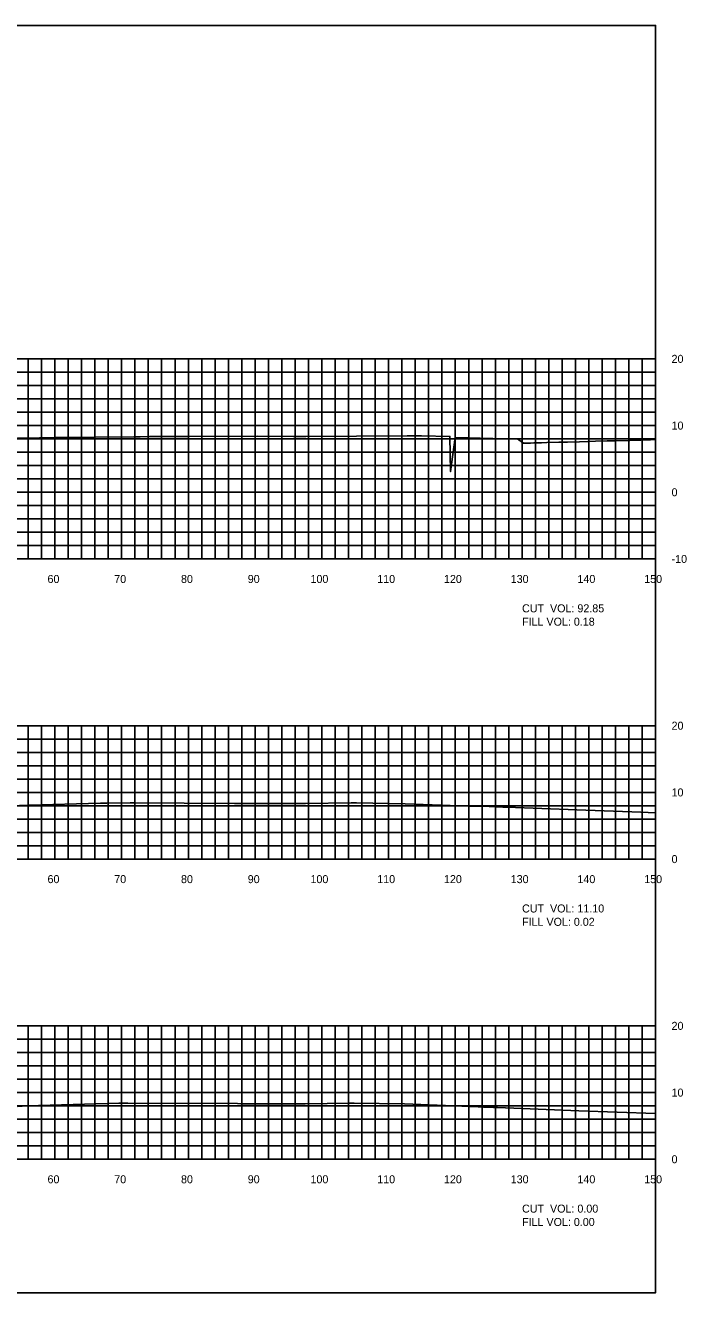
# Model space of a CAD drawing. Extents: x 1800876 to 1802446, y 250079 to 250269.
# Drawn here: x 1802346.6 to 1802445.7, y 250079.4 to 250269.4 of the extents above; entities that cross this region are included whole.
import ezdxf

# ---------------------------------------------------------------- set-up
doc = ezdxf.new("R2010")
doc.units = 0
for name, color, linetype in [('10', 7, 'Continuous'), ('31', 7, 'Continuous'), ('60', 7, 'Continuous'), ('ANNO-TXT', 7, 'Continuous'), ('Level 62', 7, 'Continuous'), ('M-ROADS', 7, 'Continuous')]:
    doc.layers.add(name, color=color, linetype=linetype)

msp = doc.modelspace()

# ---------------------------------------------------------------- linework, layer by layer
msp.add_lwpolyline([(1802141, 250079.43), (1802441, 250079.43), (1802441, 250269.43), (1802141, 250269.43)], close=True)
at = {"layer": '60'}
for p, q in [((1802441, 250189.43), (1802441, 250219.43)), ((1802441.06, 250219.43), (1802441, 250219.43)), ((1802441.06, 250209.43), (1802441, 250209.43)), ((1802441.06, 250199.43), (1802441, 250199.43)), ((1802141, 250189.43), (1802441, 250189.43)), ((1802351, 250189.37), (1802351, 250189.43)), ((1802361, 250189.37), (1802361, 250189.43)), ((1802371, 250189.37), (1802371, 250189.43)), ((1802381, 250189.37), (1802381, 250189.43)), ((1802391, 250189.37), (1802391, 250189.43)), ((1802401, 250189.37), (1802401, 250189.43)), ((1802411, 250189.37), (1802411, 250189.43)), ((1802421, 250189.37), (1802421, 250189.43)), ((1802431, 250189.37), (1802431, 250189.43)), ((1802441, 250189.37), (1802441, 250189.43)), ((1802441.06, 250189.43), (1802441, 250189.43)), ((1802441, 250144.43), (1802441, 250164.43)), ((1802441.06, 250164.43), (1802441, 250164.43)), ((1802441.06, 250154.43), (1802441, 250154.43)), ((1802141, 250144.43), (1802441, 250144.43)), ((1802351, 250144.37), (1802351, 250144.43)), ((1802361, 250144.37), (1802361, 250144.43)), ((1802371, 250144.37), (1802371, 250144.43)), ((1802381, 250144.37), (1802381, 250144.43)), ((1802391, 250144.37), (1802391, 250144.43)), ((1802401, 250144.37), (1802401, 250144.43)), ((1802411, 250144.37), (1802411, 250144.43)), ((1802421, 250144.37), (1802421, 250144.43)), ((1802431, 250144.37), (1802431, 250144.43)), ((1802441, 250144.37), (1802441, 250144.43)), ((1802441.06, 250144.43), (1802441, 250144.43)), ((1802441, 250099.43), (1802441, 250119.43)), ((1802441.06, 250119.43), (1802441, 250119.43)), ((1802441.06, 250109.43), (1802441, 250109.43)), ((1802141, 250099.43), (1802441, 250099.43)), ((1802351, 250099.37), (1802351, 250099.43)), ((1802361, 250099.37), (1802361, 250099.43)), ((1802371, 250099.37), (1802371, 250099.43)), ((1802381, 250099.37), (1802381, 250099.43)), ((1802391, 250099.37), (1802391, 250099.43)), ((1802401, 250099.37), (1802401, 250099.43)), ((1802411, 250099.37), (1802411, 250099.43)), ((1802421, 250099.37), (1802421, 250099.43)), ((1802431, 250099.37), (1802431, 250099.43)), ((1802441, 250099.37), (1802441, 250099.43)), ((1802441.06, 250099.43), (1802441, 250099.43))]:
    msp.add_line(p, q, dxfattribs=at)
at = {"layer": 'Level 62'}
for p, q in [((1802141, 250219.43), (1802441, 250219.43)), ((1802347, 250189.43), (1802347, 250219.43)), ((1802349, 250189.43), (1802349, 250219.43)), ((1802351, 250189.43), (1802351, 250219.43)), ((1802353, 250189.43), (1802353, 250219.43)), ((1802355, 250189.43), (1802355, 250219.43)), ((1802357, 250189.43), (1802357, 250219.43)), ((1802359, 250189.43), (1802359, 250219.43)), ((1802361, 250189.43), (1802361, 250219.43)), ((1802363, 250189.43), (1802363, 250219.43)), ((1802365, 250189.43), (1802365, 250219.43)), ((1802367, 250189.43), (1802367, 250219.43)), ((1802369, 250189.43), (1802369, 250219.43)), ((1802371, 250189.43), (1802371, 250219.43)), ((1802373, 250189.43), (1802373, 250219.43)), ((1802375, 250189.43), (1802375, 250219.43)), ((1802377, 250189.43), (1802377, 250219.43)), ((1802379, 250189.43), (1802379, 250219.43)), ((1802381, 250189.43), (1802381, 250219.43)), ((1802383, 250189.43), (1802383, 250219.43)), ((1802385, 250189.43), (1802385, 250219.43)), ((1802387, 250189.43), (1802387, 250219.43)), ((1802389, 250189.43), (1802389, 250219.43)), ((1802391, 250189.43), (1802391, 250219.43)), ((1802393, 250189.43), (1802393, 250219.43)), ((1802395, 250189.43), (1802395, 250219.43)), ((1802397, 250189.43), (1802397, 250219.43)), ((1802399, 250189.43), (1802399, 250219.43)), ((1802401, 250189.43), (1802401, 250219.43)), ((1802403, 250189.43), (1802403, 250219.43)), ((1802405, 250189.43), (1802405, 250219.43)), ((1802407, 250189.43), (1802407, 250219.43)), ((1802409, 250189.43), (1802409, 250219.43)), ((1802411, 250189.43), (1802411, 250219.43)), ((1802413, 250189.43), (1802413, 250219.43)), ((1802415, 250189.43), (1802415, 250219.43)), ((1802417, 250189.43), (1802417, 250219.43)), ((1802419, 250189.43), (1802419, 250219.43)), ((1802421, 250189.43), (1802421, 250219.43)), ((1802423, 250189.43), (1802423, 250219.43)), ((1802425, 250189.43), (1802425, 250219.43)), ((1802427, 250189.43), (1802427, 250219.43)), ((1802429, 250189.43), (1802429, 250219.43)), ((1802431, 250189.43), (1802431, 250219.43)), ((1802433, 250189.43), (1802433, 250219.43)), ((1802435, 250189.43), (1802435, 250219.43)), ((1802437, 250189.43), (1802437, 250219.43)), ((1802439, 250189.43), (1802439, 250219.43)), ((1802441, 250189.43), (1802441, 250219.43)), ((1802141, 250217.43), (1802441, 250217.43)), ((1802141, 250215.43), (1802441, 250215.43)), ((1802141, 250213.43), (1802441, 250213.43)), ((1802141, 250211.43), (1802441, 250211.43)), ((1802141, 250209.43), (1802441, 250209.43)), ((1802141, 250207.43), (1802441, 250207.43)), ((1802141, 250205.43), (1802441, 250205.43)), ((1802141, 250203.43), (1802441, 250203.43)), ((1802141, 250201.43), (1802441, 250201.43)), ((1802141, 250199.43), (1802441, 250199.43)), ((1802141, 250197.43), (1802441, 250197.43)), ((1802141, 250195.43), (1802441, 250195.43)), ((1802141, 250193.43), (1802441, 250193.43)), ((1802141, 250191.43), (1802441, 250191.43)), ((1802141, 250189.43), (1802441, 250189.43)), ((1802141, 250164.43), (1802441, 250164.43)), ((1802347, 250144.43), (1802347, 250164.43)), ((1802349, 250144.43), (1802349, 250164.43)), ((1802351, 250144.43), (1802351, 250164.43)), ((1802353, 250144.43), (1802353, 250164.43)), ((1802355, 250144.43), (1802355, 250164.43)), ((1802357, 250144.43), (1802357, 250164.43)), ((1802359, 250144.43), (1802359, 250164.43)), ((1802361, 250144.43), (1802361, 250164.43)), ((1802363, 250144.43), (1802363, 250164.43)), ((1802365, 250144.43), (1802365, 250164.43)), ((1802367, 250144.43), (1802367, 250164.43)), ((1802369, 250144.43), (1802369, 250164.43)), ((1802371, 250144.43), (1802371, 250164.43)), ((1802373, 250144.43), (1802373, 250164.43)), ((1802375, 250144.43), (1802375, 250164.43)), ((1802377, 250144.43), (1802377, 250164.43)), ((1802379, 250144.43), (1802379, 250164.43)), ((1802381, 250144.43), (1802381, 250164.43)), ((1802383, 250144.43), (1802383, 250164.43)), ((1802385, 250144.43), (1802385, 250164.43)), ((1802387, 250144.43), (1802387, 250164.43)), ((1802389, 250144.43), (1802389, 250164.43)), ((1802391, 250144.43), (1802391, 250164.43)), ((1802393, 250144.43), (1802393, 250164.43)), ((1802395, 250144.43), (1802395, 250164.43)), ((1802397, 250144.43), (1802397, 250164.43)), ((1802399, 250144.43), (1802399, 250164.43)), ((1802401, 250144.43), (1802401, 250164.43)), ((1802403, 250144.43), (1802403, 250164.43)), ((1802405, 250144.43), (1802405, 250164.43)), ((1802407, 250144.43), (1802407, 250164.43)), ((1802409, 250144.43), (1802409, 250164.43)), ((1802411, 250144.43), (1802411, 250164.43)), ((1802413, 250144.43), (1802413, 250164.43)), ((1802415, 250144.43), (1802415, 250164.43)), ((1802417, 250144.43), (1802417, 250164.43)), ((1802419, 250144.43), (1802419, 250164.43)), ((1802421, 250144.43), (1802421, 250164.43)), ((1802423, 250144.43), (1802423, 250164.43)), ((1802425, 250144.43), (1802425, 250164.43)), ((1802427, 250144.43), (1802427, 250164.43)), ((1802429, 250144.43), (1802429, 250164.43)), ((1802431, 250144.43), (1802431, 250164.43)), ((1802433, 250144.43), (1802433, 250164.43)), ((1802435, 250144.43), (1802435, 250164.43)), ((1802437, 250144.43), (1802437, 250164.43)), ((1802439, 250144.43), (1802439, 250164.43)), ((1802441, 250144.43), (1802441, 250164.43)), ((1802141, 250162.43), (1802441, 250162.43)), ((1802141, 250160.43), (1802441, 250160.43)), ((1802141, 250158.43), (1802441, 250158.43)), ((1802141, 250156.43), (1802441, 250156.43)), ((1802141, 250154.43), (1802441, 250154.43)), ((1802141, 250152.43), (1802441, 250152.43)), ((1802141, 250150.43), (1802441, 250150.43)), ((1802141, 250148.43), (1802441, 250148.43)), ((1802141, 250146.43), (1802441, 250146.43)), ((1802141, 250144.43), (1802441, 250144.43)), ((1802141, 250119.43), (1802441, 250119.43)), ((1802347, 250099.43), (1802347, 250119.43)), ((1802349, 250099.43), (1802349, 250119.43)), ((1802351, 250099.43), (1802351, 250119.43)), ((1802353, 250099.43), (1802353, 250119.43)), ((1802355, 250099.43), (1802355, 250119.43)), ((1802357, 250099.43), (1802357, 250119.43)), ((1802359, 250099.43), (1802359, 250119.43)), ((1802361, 250099.43), (1802361, 250119.43)), ((1802363, 250099.43), (1802363, 250119.43)), ((1802365, 250099.43), (1802365, 250119.43)), ((1802367, 250099.43), (1802367, 250119.43)), ((1802369, 250099.43), (1802369, 250119.43)), ((1802371, 250099.43), (1802371, 250119.43)), ((1802373, 250099.43), (1802373, 250119.43)), ((1802375, 250099.43), (1802375, 250119.43)), ((1802377, 250099.43), (1802377, 250119.43)), ((1802379, 250099.43), (1802379, 250119.43)), ((1802381, 250099.43), (1802381, 250119.43)), ((1802383, 250099.43), (1802383, 250119.43)), ((1802385, 250099.43), (1802385, 250119.43)), ((1802387, 250099.43), (1802387, 250119.43)), ((1802389, 250099.43), (1802389, 250119.43)), ((1802391, 250099.43), (1802391, 250119.43)), ((1802393, 250099.43), (1802393, 250119.43)), ((1802395, 250099.43), (1802395, 250119.43)), ((1802397, 250099.43), (1802397, 250119.43)), ((1802399, 250099.43), (1802399, 250119.43)), ((1802401, 250099.43), (1802401, 250119.43)), ((1802403, 250099.43), (1802403, 250119.43)), ((1802405, 250099.43), (1802405, 250119.43)), ((1802407, 250099.43), (1802407, 250119.43)), ((1802409, 250099.43), (1802409, 250119.43)), ((1802411, 250099.43), (1802411, 250119.43)), ((1802413, 250099.43), (1802413, 250119.43)), ((1802415, 250099.43), (1802415, 250119.43)), ((1802417, 250099.43), (1802417, 250119.43)), ((1802419, 250099.43), (1802419, 250119.43)), ((1802421, 250099.43), (1802421, 250119.43)), ((1802423, 250099.43), (1802423, 250119.43)), ((1802425, 250099.43), (1802425, 250119.43)), ((1802427, 250099.43), (1802427, 250119.43)), ((1802429, 250099.43), (1802429, 250119.43)), ((1802431, 250099.43), (1802431, 250119.43)), ((1802433, 250099.43), (1802433, 250119.43)), ((1802435, 250099.43), (1802435, 250119.43)), ((1802437, 250099.43), (1802437, 250119.43)), ((1802439, 250099.43), (1802439, 250119.43)), ((1802441, 250099.43), (1802441, 250119.43)), ((1802141, 250117.43), (1802441, 250117.43)), ((1802141, 250115.43), (1802441, 250115.43)), ((1802141, 250113.43), (1802441, 250113.43)), ((1802141, 250111.43), (1802441, 250111.43)), ((1802141, 250109.43), (1802441, 250109.43)), ((1802141, 250107.43), (1802441, 250107.43)), ((1802141, 250105.43), (1802441, 250105.43)), ((1802141, 250103.43), (1802441, 250103.43)), ((1802141, 250101.43), (1802441, 250101.43)), ((1802141, 250099.43), (1802441, 250099.43))]:
    msp.add_line(p, q, dxfattribs=at)
at = {"layer": 'M-ROADS'}
for points in [[(1802338.69, 250207.45), (1802348.71, 250207.61), (1802349.3, 250207.61), (1802349.49, 250207.61), (1802349.62, 250207.61), (1802349.8, 250207.61), (1802350.93, 250207.63), (1802362.82, 250207.75), (1802363.27, 250207.75), (1802363.32, 250207.75), (1802363.76, 250207.76), (1802365.19, 250207.78), (1802370.92, 250207.8), (1802371.12, 250207.8), (1802381.42, 250207.83), (1802386.73, 250207.79), (1802386.84, 250207.79), (1802387.23, 250207.79), (1802388.59, 250207.78), (1802403.8, 250207.9), (1802405.49, 250207.91), (1802405.91, 250207.91), (1802410.2, 250207.8), (1802410.28, 250202.52), (1802410.99, 250207.62), (1802420.36, 250207.38), (1802420.52, 250207.29), (1802421.22, 250206.8), (1802422.27, 250206.8), (1802422.74, 250206.85), (1802423.75, 250206.86), (1802423.79, 250206.86), (1802423.93, 250206.86), (1802424.72, 250206.88), (1802426.49, 250206.92), (1802427.2, 250206.94), (1802427.82, 250206.95), (1802429.62, 250207), (1802430.86, 250207.04), (1802430.93, 250207.04), (1802431.99, 250207.07), (1802432, 250207.07), (1802433.74, 250207.12), (1802434.04, 250207.13), (1802434.66, 250207.14), (1802434.95, 250207.16), (1802437.14, 250207.21), (1802437.48, 250207.23), (1802438.76, 250207.26), (1802438.81, 250207.26), (1802439.97, 250207.29), (1802440.22, 250207.3), (1802441, 250207.32)], [(1802345.69, 250152.45), (1802347.08, 250152.54), (1802357.86, 250152.84), (1802358.07, 250152.84), (1802358.8, 250152.84), (1802362.29, 250152.85), (1802362.35, 250152.85), (1802362.84, 250152.85), (1802377.89, 250152.77), (1802378.39, 250152.77), (1802378.5, 250152.77), (1802384, 250152.76), (1802384.49, 250152.77), (1802384.82, 250152.77), (1802388.57, 250152.76), (1802395.38, 250152.86), (1802395.87, 250152.87), (1802396.17, 250152.87), (1802403.49, 250152.74), (1802412.94, 250152.38), (1802413.12, 250152.37), (1802413.7, 250152.35), (1802416.07, 250152.34), (1802418.12, 250152.2), (1802418.7, 250152.21), (1802429.23, 250151.8), (1802438.81, 250151.49), (1802441, 250151.36)], [(1802345.39, 250107.33), (1802346.85, 250107.42), (1802360.57, 250107.84), (1802360.6, 250107.84), (1802361.32, 250107.84), (1802361.37, 250107.84), (1802361.42, 250107.84), (1802361.92, 250107.84), (1802378.37, 250107.77), (1802378.88, 250107.76), (1802378.96, 250107.76), (1802383.45, 250107.76), (1802384.02, 250107.76), (1802384.33, 250107.76), (1802388.51, 250107.76), (1802395.11, 250107.86), (1802395.59, 250107.86), (1802395.85, 250107.86), (1802403.38, 250107.72), (1802414.43, 250107.27), (1802414.53, 250107.27), (1802415.24, 250107.24), (1802416.07, 250107.23), (1802416.7, 250107.19), (1802417.34, 250107.19), (1802429.51, 250106.69), (1802441, 250106.28)]]:
    msp.add_lwpolyline(points, dxfattribs=at)

# ---------------------------------------------------------------- texts
at = {"layer": '10'}
for s, p in [('60', (1802349.9, 250185.83)), ('70', (1802359.9, 250185.83)), ('80', (1802369.9, 250185.83)), ('90', (1802379.9, 250185.83)), ('100', (1802389.3, 250185.83)), ('110', (1802399.3, 250185.83)), ('120', (1802409.3, 250185.83)), ('130', (1802419.3, 250185.83)), ('140', (1802429.3, 250185.83)), ('150', (1802439.3, 250185.83)), ('60', (1802349.9, 250140.83)), ('70', (1802359.9, 250140.83)), ('80', (1802369.9, 250140.83)), ('90', (1802379.9, 250140.83)), ('100', (1802389.3, 250140.83)), ('110', (1802399.3, 250140.83)), ('120', (1802409.3, 250140.83)), ('130', (1802419.3, 250140.83)), ('140', (1802429.3, 250140.83)), ('150', (1802439.3, 250140.83)), ('60', (1802349.9, 250095.83)), ('70', (1802359.9, 250095.83)), ('80', (1802369.9, 250095.83)), ('90', (1802379.9, 250095.83)), ('100', (1802389.3, 250095.83)), ('110', (1802399.3, 250095.83)), ('120', (1802409.3, 250095.83)), ('130', (1802419.3, 250095.83)), ('140', (1802429.3, 250095.83)), ('150', (1802439.3, 250095.83))]:
    msp.add_text(s, height=1.2, dxfattribs=at).set_placement(p)
at = {"layer": '31'}
for s, p in [('20', (1802443.4, 250218.83)), ('10', (1802443.4, 250208.83)), ('0', (1802443.4, 250198.83)), ('-10', (1802443.4, 250188.83)), ('20', (1802443.4, 250163.83)), ('10', (1802443.4, 250153.83)), ('0', (1802443.4, 250143.83)), ('20', (1802443.4, 250118.83)), ('10', (1802443.4, 250108.83)), ('0', (1802443.4, 250098.83))]:
    msp.add_text(s, height=1.2, dxfattribs=at).set_placement(p)
at = {"layer": 'ANNO-TXT'}
for s, p in [('CUT  VOL: 92.85', (1802421, 250181.43)), ('FILL VOL: 0.18', (1802421, 250179.43)), ('CUT  VOL: 11.10', (1802421, 250136.43)), ('FILL VOL: 0.02', (1802421, 250134.43)), ('CUT  VOL: 0.00', (1802421, 250091.43)), ('FILL VOL: 0.00', (1802421, 250089.43))]:
    msp.add_text(s, height=1.2, dxfattribs=at).set_placement(p)

doc.saveas('drawing.dxf')
